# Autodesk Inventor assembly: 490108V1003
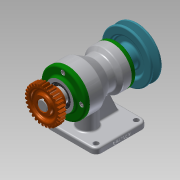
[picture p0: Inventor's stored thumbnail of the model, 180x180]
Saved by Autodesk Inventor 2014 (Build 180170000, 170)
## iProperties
Created: 2019-01
Part Number: 490108V1003
Document SubType Name: Assembly
Designer: 601-05
Author: 601-05
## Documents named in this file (15)
- C:\Users\601-05\Desktop\490108V1003\490108V1003.iam
- C:\Users\601-05\Desktop\490108V1003\490108V1003.ipt
- C:\Users\601-05\Desktop\490108V1003\V-벨트풀리.ipt
- C:\Users\601-05\Desktop\490108V1003\뒤커버.ipt
- C:\Users\601-05\Desktop\490108V1003\멈춤나사 M3.ipt
- C:\Users\601-05\Desktop\490108V1003\베어링 6203.ipt
- C:\Users\601-05\Desktop\490108V1003\베어링 6205.ipt
- C:\Users\601-05\Desktop\490108V1003\볼트 M4.ipt
- C:\Users\601-05\Desktop\490108V1003\스퍼기어.ipt
- C:\Users\601-05\Desktop\490108V1003\앞커버.ipt
- C:\Users\601-05\Desktop\490108V1003\오일 실 17 30 8.ipt
- C:\Users\601-05\Desktop\490108V1003\오일 실 25 38 8.ipt
- C:\Users\601-05\Desktop\490108V1003\축.ipt
- C:\Users\601-05\Desktop\490108V1003\키 5 x 5 x 20.ipt
- C:\Users\601-05\Desktop\490108V1003\키 6 x 6 x 18.ipt
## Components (2 placed, 2 different names)
1. 490108V1003:1
2. V-벨트풀리:1
